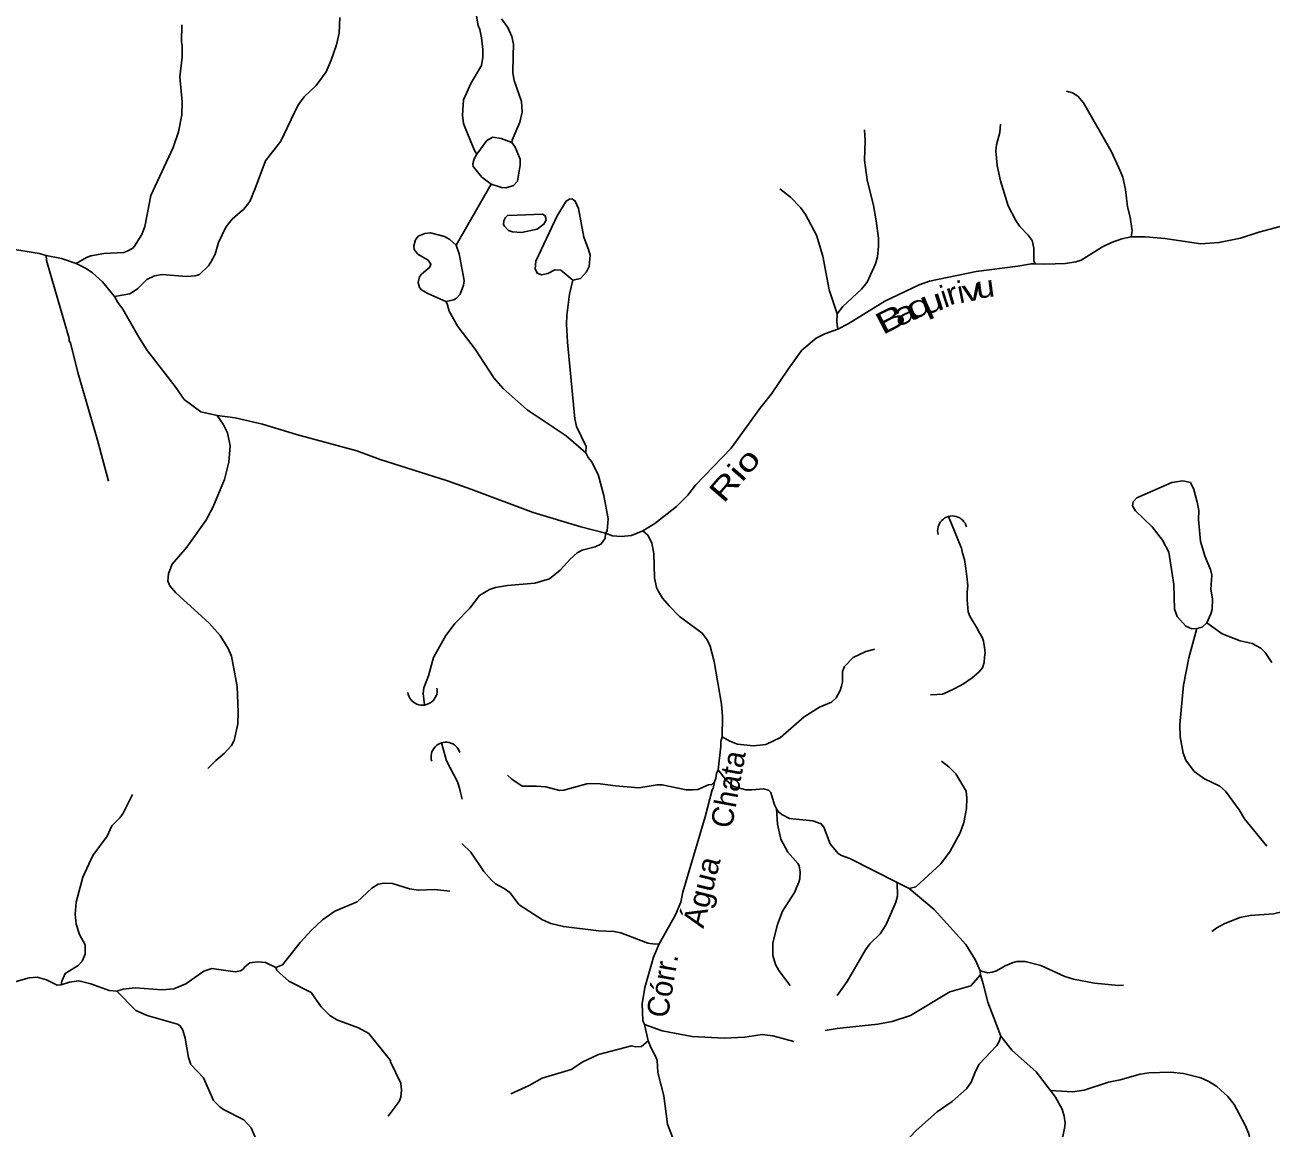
# Model space of a CAD drawing. Extents: x 346.5 to 372.4, y 7400.3 to 7428.2.
# Drawn here: x 354.02 to 358.605, y 7406.713 to 7410.774 of the extents above; entities that cross this region are included whole.
import ezdxf
from ezdxf.enums import TextEntityAlignment as Align

# ---------------------------------------------------------------- set-up
doc = ezdxf.new("R2010")
doc.units = 0
doc.header["$LTSCALE"] = 0.032
for name, color, linetype, lineweight in [('1', 7, 'Continuous', 25), ('11', 7, 'Continuous', 25), ('2', 7, 'Continuous', 25), ('7', 7, 'Continuous', 25)]:
    doc.layers.add(name, color=color, linetype=linetype, lineweight=lineweight)
doc.layers.add('61', color=7, linetype='Continuous')

msp = doc.modelspace()

# ---------------------------------------------------------------- linework, layer by layer
at = {"layer": '1'}
msp.add_lwpolyline([(354.098, 7409.9245), (354.0997, 7409.9069), (354.1829, 7409.6193), (354.1829, 7409.6105), (354.1877, 7409.6033), (354.2148, 7409.4942), (354.2873, 7409.2455), (354.3272, 7409.0949)], dxfattribs=at)
at = {"layer": '11'}
for centre, start, end in [((357.4324, 7408.9121), 14.923, 195.626), ((355.4826, 7408.3238), 188.0692, 8.7722), ((355.5686, 7408.0796), 16.6975, 197.4005)]:
    msp.add_arc(centre, 0.0541, start, end, dxfattribs=at)
at = {"layer": '2'}
for points in [[(355.6824, 7410.2983), (355.72, 7410.3486), (355.7413, 7410.3602), (355.7728, 7410.3554), (355.8114, 7410.3405), (355.8241, 7410.324), (355.8422, 7410.2791), (355.8417, 7410.2571), (355.8329, 7410.1986), (355.8173, 7410.1829), (355.7911, 7410.1738), (355.7732, 7410.1747), (355.7357, 7410.1873), (355.7013, 7410.2133), (355.6696, 7410.2527), (355.6686, 7410.2621), (355.673, 7410.2802)], [(355.9442, 7409.8591), (355.9202, 7409.8538), (355.9049, 7409.8594), (355.8977, 7409.8755), (355.8996, 7409.9039), (355.9788, 7410.0713), (356.012, 7410.1253), (356.0236, 7410.1327), (356.0334, 7410.133), (356.0447, 7410.1254), (356.0569, 7410.0983), (356.0767, 7409.9922), (356.0943, 7409.9475), (356.0996, 7409.9256), (356.0958, 7409.8847), (356.0863, 7409.8648), (356.0642, 7409.8398), (356.036, 7409.8343), (355.992, 7409.8711), (355.9697, 7409.8727)], [(355.8315, 7410.0737), (355.9249, 7410.0767), (355.9344, 7410.0707), (355.9377, 7410.057), (355.9308, 7410.0414), (355.9048, 7410.022), (355.8474, 7410.0095), (355.8136, 7410.0122), (355.799, 7410.0171), (355.7841, 7410.0324), (355.7812, 7410.0391), (355.7826, 7410.0524), (355.7879, 7410.0644), (355.796, 7410.0724)], [(355.5687, 7409.7553), (355.5025, 7409.7855), (355.4795, 7409.7985), (355.4715, 7409.8067), (355.4669, 7409.8261), (355.4721, 7409.8462), (355.4795, 7409.8566), (355.5098, 7409.8819), (355.5137, 7409.8929), (355.5036, 7409.9077), (355.466, 7409.9303), (355.4523, 7409.9469), (355.4511, 7409.9605), (355.4576, 7409.9827), (355.4675, 7409.9955), (355.492, 7410.0055), (355.5121, 7410.0083), (355.5636, 7409.9947), (355.5834, 7409.9838), (355.6064, 7409.9625), (355.6178, 7409.9315), (355.6357, 7409.8333), (355.634, 7409.8158), (355.6217, 7409.782), (355.6085, 7409.768), (355.5986, 7409.7623)], [(358.2394, 7409.0893), (358.2805, 7409.0955), (358.3083, 7409.089), (358.3204, 7409.0642), (358.3333, 7409.0172), (358.3391, 7408.9863), (358.3378, 7408.9531), (358.3449, 7408.8726), (358.3623, 7408.8156), (358.3825, 7408.7694), (358.3868, 7408.7487), (358.3833, 7408.697), (358.39, 7408.6613), (358.388, 7408.6224), (358.3839, 7408.606), (358.3688, 7408.5728), (358.351, 7408.5574), (358.3322, 7408.5523), (358.3131, 7408.5512), (358.2917, 7408.5612), (358.2597, 7408.5967), (358.2492, 7408.6229), (358.2476, 7408.7145), (358.2289, 7408.8335), (358.2061, 7408.8777), (358.1673, 7408.9262), (358.1064, 7408.9856), (358.0951, 7409.0038), (358.0978, 7409.0184), (358.1118, 7409.0333)]]:
    msp.add_lwpolyline(points, close=True, dxfattribs=at)
at = {"layer": '7'}
msp.add_line((355.7357, 7410.1873), (355.6064, 7409.9625), dxfattribs=at)
for points in [[(355.6796, 7410.8187), (355.6875, 7410.7709), (355.6939, 7410.7565), (355.7003, 7410.7262), (355.7051, 7410.6832), (355.7051, 7410.6545), (355.7003, 7410.6242), (355.662, 7410.5605), (355.6333, 7410.4975), (355.6301, 7410.4409), (355.6341, 7410.4107), (355.6397, 7410.3947), (355.6741, 7410.3111), (355.6824, 7410.2983)], [(354.5973, 7410.7733), (354.5957, 7410.7119), (354.5989, 7410.6976), (354.5989, 7410.6545), (354.5901, 7410.5828), (354.5989, 7410.4903), (354.5973, 7410.4425), (354.5846, 7410.3804), (354.5654, 7410.323), (354.4833, 7410.1461), (354.4618, 7410.0313), (354.4507, 7410.0026), (354.4236, 7409.9596), (354.4172, 7409.9524), (354.3965, 7409.9404), (354.3837, 7409.9365), (354.3104, 7409.9317), (354.2626, 7409.9237), (354.2467, 7409.9181), (354.209, 7409.895)], [(355.1791, 7410.8012), (355.1759, 7410.7438), (355.1663, 7410.7007), (355.1472, 7410.6434), (355.1281, 7410.6003), (355.0914, 7410.5509), (355.0476, 7410.5087), (355.0245, 7410.4776), (354.9623, 7410.3453), (354.9049, 7410.2736), (354.8667, 7410.1716), (354.8475, 7410.1238), (354.8252, 7410.0951), (354.8125, 7410.0847), (354.783, 7410.0592), (354.7599, 7410.0297), (354.7328, 7409.9723), (354.72, 7409.9293), (354.7041, 7409.9006), (354.6953, 7409.8863), (354.6627, 7409.8552), (354.6467, 7409.8504), (354.6149, 7409.848), (354.5256, 7409.8544), (354.4969, 7409.8504), (354.4682, 7409.8368), (354.4339, 7409.8026), (354.4061, 7409.7842), (354.3493, 7409.7734)], [(355.7736, 7410.7964), (355.7975, 7410.7637), (355.8119, 7410.731), (355.8182, 7410.7023), (355.8166, 7410.6593), (355.815, 7410.5971), (355.8206, 7410.5685), (355.8469, 7410.4919), (355.8501, 7410.4529), (355.8405, 7410.4154), (355.8124, 7410.3496), (355.8114, 7410.3405)], [(357.8528, 7410.5302), (357.8744, 7410.523), (357.8943, 7410.5111), (357.915, 7410.4872), (358.0162, 7410.3086), (358.0449, 7410.2481), (358.0592, 7410.2138), (358.0696, 7410.1684), (358.0768, 7410.1046), (358.0863, 7410.0664), (358.0935, 7410.0154), (358.0908, 7409.9932)], [(357.6098, 7410.4083), (357.6074, 7410.3772), (357.5946, 7410.3326), (357.5922, 7410.3102), (357.5978, 7410.256), (357.609, 7410.2003), (357.6377, 7410.1078), (357.6663, 7410.0536), (357.6807, 7410.0313), (357.7118, 7409.9994), (357.7261, 7409.9795), (357.7325, 7409.9516), (357.7321, 7409.9056), (357.7377, 7409.8945)], [(357.1093, 7410.3875), (357.1117, 7410.3469), (357.1093, 7410.2752), (357.1188, 7410.2034), (357.142, 7410.1094), (357.1523, 7410.052), (357.1603, 7409.9883), (357.1611, 7409.9596), (357.1571, 7409.9197), (357.1499, 7409.8942), (357.1188, 7409.8273), (357.0981, 7409.801), (357.0296, 7409.7372), (357.0087, 7409.7101)], [(356.7977, 7410.17), (356.8367, 7410.1397), (356.8742, 7410.1014), (356.8917, 7410.0759), (356.9324, 7409.9994), (356.9555, 7409.9229), (356.9786, 7409.7986), (357.0087, 7409.7101)], [(358.0908, 7409.9932), (358.1437, 7409.993), (358.2139, 7409.9875), (358.3462, 7409.9675), (358.4131, 7409.9723), (358.4928, 7409.989), (358.5597, 7410.0106), (358.7351, 7410.0568)], [(357.7377, 7409.8945), (357.7724, 7409.8934), (357.8489, 7409.8958), (357.8871, 7409.9014), (357.9062, 7409.9078), (357.9851, 7409.9564), (358.0186, 7409.9723), (358.0561, 7409.9859), (358.0908, 7409.9932)], [(353.9677, 7409.95), (354.0729, 7409.9317), (354.098, 7409.9245), (354.1542, 7409.9141), (354.209, 7409.895)], [(354.209, 7409.895), (354.2458, 7409.8775), (354.2682, 7409.8608), (354.3056, 7409.8281), (354.3431, 7409.781), (354.3493, 7409.7734)], [(357.0109, 7409.6543), (357.0487, 7409.6735), (357.1842, 7409.7571), (357.3109, 7409.8169), (357.3484, 7409.8305), (357.5205, 7409.8655), (357.6735, 7409.8854), (357.7232, 7409.8945), (357.7377, 7409.8945)], [(356.036, 7409.8343), (356.0238, 7409.7827), (356.0143, 7409.7046), (356.0127, 7409.6727), (356.0159, 7409.6057), (356.043, 7409.3236), (356.0501, 7409.2949), (356.0846, 7409.2216), (356.0839, 7409.1989)], [(354.3493, 7409.7734), (354.3614, 7409.7516), (354.3805, 7409.7269), (354.4387, 7409.6241), (354.4714, 7409.5739), (354.5734, 7409.4432), (354.6061, 7409.3945), (354.6674, 7409.3491), (354.728, 7409.3364)], [(355.5687, 7409.7553), (355.5741, 7409.7471), (355.5807, 7409.7205), (355.6126, 7409.6631), (355.6764, 7409.5802), (355.7449, 7409.475), (355.78, 7409.4352), (355.8676, 7409.3571), (356.0119, 7409.2614), (356.0839, 7409.1989)], [(357.0087, 7409.7101), (357.0068, 7409.679), (357.0109, 7409.6543)], [(356.2933, 7408.9116), (356.3379, 7408.9379), (356.4175, 7409.0016), (356.459, 7409.0431), (356.4877, 7409.0797), (356.6192, 7409.216), (356.7236, 7409.3619), (356.7666, 7409.4161), (356.8279, 7409.5069), (356.879, 7409.5762), (356.9308, 7409.6201), (356.9627, 7409.6368), (357.0109, 7409.6543)], [(354.728, 7409.3364), (354.7495, 7409.3045), (354.7655, 7409.2726), (354.7758, 7409.2248), (354.7702, 7409.1642), (354.7543, 7409.1005), (354.7121, 7408.9969), (354.6858, 7408.9491), (354.6156, 7408.8518), (354.5614, 7408.7889), (354.5487, 7408.7546), (354.5455, 7408.7259), (354.5535, 7408.7092), (354.575, 7408.6829), (354.6985, 7408.5721), (354.7384, 7408.5259), (354.7679, 7408.4789), (354.7798, 7408.4502), (354.8013, 7408.3386), (354.8053, 7408.2446), (354.8029, 7408.2015), (354.7894, 7408.1394), (354.7806, 7408.121), (354.7543, 7408.0931), (354.7224, 7408.066), (354.693, 7408.0366)], [(354.728, 7409.3364), (354.7934, 7409.3268), (354.8938, 7409.3037), (355.0197, 7409.2662), (355.2413, 7409.2064), (355.3273, 7409.1746), (355.5744, 7409.0957), (355.6604, 7409.0646), (355.89, 7408.9785), (356.0653, 7408.9259), (356.1567, 7408.9023)], [(356.0839, 7409.1989), (356.0928, 7409.1811), (356.1051, 7409.1666), (356.129, 7409.1188), (356.1505, 7409.0415), (356.1665, 7408.9554), (356.1623, 7408.9119), (356.1567, 7408.9023)], [(357.4182, 7408.9643), (357.4644, 7408.8503), (357.4656, 7408.848), (357.4702, 7408.8295), (357.4767, 7408.8055), (357.4825, 7408.7733), (357.4854, 7408.7429), (357.4889, 7408.709), (357.4872, 7408.6867), (357.4866, 7408.658), (357.4889, 7408.6276), (357.4907, 7408.6136), (357.4971, 7408.5972), (357.5088, 7408.5768), (357.5211, 7408.5575), (357.5339, 7408.5335), (357.5427, 7408.5207), (357.5468, 7408.5055), (357.5503, 7408.4821), (357.5526, 7408.4634), (357.5509, 7408.4464), (357.5497, 7408.4267), (357.5433, 7408.4074), (357.5298, 7408.3911), (357.5053, 7408.3706), (357.4732, 7408.3484), (357.441, 7408.3314), (357.413, 7408.3174), (357.3966, 7408.3098), (357.375, 7408.3092), (357.3522, 7408.3081)], [(355.49, 7408.2717), (355.4891, 7408.2812), (355.4859, 7408.3131), (355.4875, 7408.3338), (355.505, 7408.3784), (355.5234, 7408.4454), (355.5688, 7408.5267), (355.6031, 7408.5721), (355.6565, 7408.6263), (355.6931, 7408.6733), (355.729, 7408.6956), (355.7513, 7408.7028), (355.7959, 7408.7108), (355.8963, 7408.7187), (355.9497, 7408.7347), (355.9896, 7408.7673), (356.0262, 7408.8072), (356.0525, 7408.8303), (356.0701, 7408.8407), (356.1179, 7408.8526), (356.1394, 7408.8622), (356.1546, 7408.8831), (356.1567, 7408.9023)], [(356.1567, 7408.9023), (356.1826, 7408.8935), (356.2135, 7408.8901), (356.2518, 7408.894), (356.2933, 7408.9116)], [(356.2933, 7408.9116), (356.3131, 7408.8949), (356.3267, 7408.8662), (356.3339, 7408.8279), (356.337, 7408.7387), (356.3442, 7408.7028), (356.3514, 7408.6877), (356.3665, 7408.6637), (356.3904, 7408.635), (356.4287, 7408.596), (356.5116, 7408.5346), (356.5307, 7408.5107), (356.5419, 7408.4868), (356.5562, 7408.431), (356.5833, 7408.2732), (356.5865, 7408.2286), (356.5859, 7408.1533)], [(358.3688, 7408.5728), (358.4258, 7408.5322), (358.4912, 7408.5067), (358.5358, 7408.4964), (358.5669, 7408.4797), (358.5828, 7408.4637), (358.6083, 7408.4263)], [(358.3322, 7408.5523), (358.3023, 7408.4438), (358.2832, 7408.3434), (358.2696, 7408.1983), (358.2712, 7408.1537), (358.2816, 7408.0931), (358.2919, 7408.0676), (358.3222, 7408.0262), (358.3605, 7407.9991), (358.4163, 7407.9712), (358.4378, 7407.9529), (358.488, 7407.8843), (358.5079, 7407.8509), (358.5892, 7407.7512)], [(357.1467, 7408.4757), (357.1141, 7408.4669), (357.067, 7408.4454), (357.0352, 7408.4119), (357.028, 7408.3936), (357.028, 7408.3561), (357.0248, 7408.3402), (357.02, 7408.3243), (357.0049, 7408.2963), (356.9874, 7408.2812), (356.9435, 7408.2621), (356.8877, 7408.227), (356.8001, 7408.1513), (356.7459, 7408.125), (356.7013, 7408.1202), (356.6423, 7408.1258), (356.6136, 7408.137), (356.5859, 7408.1533)], [(355.5527, 7408.1314), (355.5712, 7408.0644), (355.6118, 7407.9879), (355.619, 7407.964), (355.6222, 7407.9489), (355.6286, 7407.9234)], [(356.5859, 7408.1533), (356.5804, 7408.1361), (356.5809, 7408.1186), (356.5711, 7408.0319)], [(357.3922, 7408.0636), (357.4201, 7408.0429), (357.4456, 7408.0166), (357.4838, 7407.9529), (357.4862, 7407.9274), (357.4846, 7407.8891), (357.4743, 7407.8381), (357.4607, 7407.7999), (357.4249, 7407.7321), (357.3898, 7407.6859), (357.2982, 7407.6014), (357.274, 7407.5952)], [(356.5711, 7408.0319), (356.5642, 7408.0181), (356.5626, 7408.0015), (356.5577, 7407.9878)], [(356.7856, 7407.8887), (356.7777, 7407.9035), (356.765, 7407.9489), (356.7562, 7407.9568), (356.7371, 7407.9624), (356.6949, 7407.9576), (356.6726, 7407.9584), (356.6269, 7407.9699), (356.6007, 7407.994), (356.5711, 7408.0319)], [(355.7959, 7408.0126), (355.8119, 7407.9975), (355.8501, 7407.9712), (355.9019, 7407.972), (355.9362, 7407.9688), (355.9872, 7407.956), (356.0031, 7407.9568), (356.0876, 7407.9808), (356.1036, 7407.9815), (356.137, 7407.9808), (356.1928, 7407.9728), (356.2789, 7407.9656), (356.3458, 7407.9768), (356.3649, 7407.976), (356.4526, 7407.9584), (356.4765, 7407.9576), (356.4956, 7407.9592), (356.5355, 7407.976), (356.5475, 7407.9779), (356.5577, 7407.9878)], [(356.5577, 7407.9878), (356.5529, 7407.963), (356.549, 7407.9584), (356.5227, 7407.8588), (356.4406, 7407.5815), (356.4339, 7407.5448), (356.4143, 7407.4978), (356.3535, 7407.3917)], [(354.4164, 7407.9409), (354.3805, 7407.87), (354.3694, 7407.8548), (354.3399, 7407.8254), (354.3232, 7407.7871), (354.2698, 7407.7162), (354.2331, 7407.6373), (354.2092, 7407.5448), (354.2044, 7407.5002), (354.2084, 7407.4635), (354.2211, 7407.4253), (354.2419, 7407.3878), (354.2419, 7407.3536), (354.2307, 7407.3281), (354.2164, 7407.3113), (354.1686, 7407.2826), (354.1562, 7407.2537), (354.1538, 7407.2408)], [(356.7856, 7407.8887), (356.7889, 7407.8317), (356.8017, 7407.776), (356.8272, 7407.7289), (356.8638, 7407.6875), (356.8686, 7407.6779), (356.8726, 7407.6564), (356.8718, 7407.6309), (356.8678, 7407.6182), (356.8511, 7407.5799), (356.808, 7407.5122), (356.7889, 7407.462), (356.7714, 7407.395), (356.7714, 7407.3488), (356.7817, 7407.3153), (356.7945, 7407.293), (356.8359, 7407.238)], [(357.2293, 7407.6166), (357.0551, 7407.705), (357.024, 7407.7162), (357.0129, 7407.7241), (356.9834, 7407.76), (356.9595, 7407.8206), (356.9499, 7407.8325), (356.9196, 7407.8445), (356.8336, 7407.8532), (356.8048, 7407.8674), (356.7918, 7407.8784), (356.7856, 7407.8887)], [(356.3535, 7407.3917), (356.3387, 7407.3902), (356.3124, 7407.3942), (356.2127, 7407.4316), (356.188, 7407.4364), (356.1306, 7407.4388), (356.0015, 7407.4548), (355.9553, 7407.4667), (355.925, 7407.4803), (355.839, 7407.5353), (355.8039, 7407.5799), (355.7832, 7407.595), (355.7521, 7407.6118), (355.7369, 7407.6261), (355.709, 7407.658), (355.6612, 7407.7289), (355.6278, 7407.7608)], [(355.5831, 7407.5855), (355.5266, 7407.591), (355.4676, 7407.5887), (355.4357, 7407.5942), (355.372, 7407.6134), (355.3417, 7407.615), (355.3194, 7407.611), (355.297, 7407.5966), (355.2428, 7407.5456), (355.16, 7407.5113), (355.1153, 7407.4795), (355.0747, 7407.442), (355.0324, 7407.3966), (354.9679, 7407.3137), (354.9434, 7407.3038)], [(357.2293, 7407.6166), (357.2304, 7407.5672), (357.2248, 7407.5448), (357.189, 7407.4627), (357.1667, 7407.4285), (357.1292, 7407.391), (357.1125, 7407.3695), (357.0455, 7407.2532), (357.0081, 7407.2014)], [(357.5352, 7407.2914), (357.5173, 7407.3313), (357.4822, 7407.3886), (357.3659, 7407.5177), (357.274, 7407.5952), (357.2293, 7407.6166)], [(358.7158, 7407.5211), (358.6857, 7407.5185), (358.6139, 7407.5018), (358.5279, 7407.4954), (358.4896, 7407.4882), (358.4322, 7407.4651), (358.4051, 7407.4508), (358.3868, 7407.4372)], [(356.3535, 7407.3917), (356.3323, 7407.3424), (356.3012, 7407.2308), (356.2916, 7407.1703), (356.294, 7407.1097), (356.2992, 7407.0949), (356.3134, 7407.0341)], [(354.3583, 7407.2173), (354.3821, 7407.2245), (354.4252, 7407.2292), (354.5256, 7407.2221), (354.5686, 7407.2252), (354.6117, 7407.2436), (354.6786, 7407.2906), (354.7073, 7407.3002), (354.7934, 7407.2882), (354.8133, 7407.2922), (354.8236, 7407.2986), (354.8292, 7407.3065), (354.8476, 7407.3209), (354.8763, 7407.3249), (354.9049, 7407.3225), (354.9434, 7407.3038)], [(354.9434, 7407.3038), (354.9474, 7407.2943), (354.9567, 7407.2842), (354.991, 7407.2539), (355.0739, 7407.2117), (355.1097, 7407.1599), (355.1424, 7407.1272), (355.1679, 7407.1121), (355.2476, 7407.0826), (355.2851, 7407.0611), (355.3656, 7406.9623), (355.3656, 7406.9567), (355.4038, 7406.8786), (355.4062, 7406.8531), (355.4038, 7406.8276), (355.3974, 7406.8108), (355.356, 7406.7567)], [(358.0616, 7407.2388), (358.0433, 7407.238), (357.9557, 7407.2468), (357.8776, 7407.2611), (357.8457, 7407.2715), (357.758, 7407.3113), (357.6998, 7407.3265), (357.6703, 7407.3265), (357.656, 7407.3225), (357.6273, 7407.3105), (357.5954, 7407.2914), (357.5795, 7407.2874), (357.5636, 7407.285), (357.5352, 7407.2914)], [(357.6107, 7407.0517), (357.5627, 7407.1766), (357.546, 7407.2436), (357.5366, 7407.2769), (357.5352, 7407.2914)], [(353.9789, 7407.2507), (354.0363, 7407.2667), (354.065, 7407.2683), (354.0992, 7407.2587), (354.1387, 7407.2394), (354.1538, 7407.2408)], [(354.1538, 7407.2408), (354.1845, 7407.2507), (354.218, 7407.2547), (354.2626, 7407.2444), (354.3303, 7407.2197), (354.3583, 7407.2173)], [(357.5366, 7407.2769), (357.5006, 7407.2364), (357.4233, 7407.2149), (357.2782, 7407.128), (357.2113, 7407.1057), (357.1587, 7407.0961), (357.0089, 7407.0802), (356.965, 7407.0722)], [(354.3583, 7407.2173), (354.4276, 7407.1456), (354.4698, 7407.128), (354.5814, 7407.0961), (354.5909, 7407.0898), (354.6005, 7407.073), (354.6101, 7407.0444), (354.622, 7406.9726), (354.6308, 7406.9471), (354.677, 7406.8977), (354.7145, 7406.8148), (354.7376, 7406.7909), (354.7503, 7406.7821), (354.8252, 7406.7439), (354.8531, 7406.7144), (354.8786, 7406.6539)], [(356.8487, 7407.0316), (356.7714, 7407.0523), (356.7331, 7407.0571), (356.6694, 7407.0483), (356.5929, 7407.0443), (356.4749, 7407.0499), (356.3649, 7407.0714), (356.2992, 7407.0949)], [(356.3134, 7407.0341), (356.2892, 7407.0133), (356.2661, 7407.0125), (356.2518, 7407.0156), (356.1306, 7406.9838), (356.0733, 7406.9567), (356.0302, 7406.9288), (355.9234, 7406.8969), (355.8756, 7406.8698), (355.8079, 7406.8387)], [(356.3134, 7407.0341), (356.324, 7407.0076), (356.3418, 7406.9758), (356.3458, 7406.9615), (356.3482, 7406.9184), (356.3713, 7406.8324), (356.3841, 7406.7272), (356.4024, 7406.6794), (356.4155, 7406.6286), (356.4203, 7406.6148)], [(357.6107, 7407.0517), (357.6049, 7407.0322), (357.5962, 7407.0172), (357.5317, 7406.9487), (357.5189, 7406.9256), (357.5014, 7406.8818), (357.4846, 7406.8571), (357.4321, 7406.8108), (357.3771, 7406.7726), (357.3006, 7406.7056), (357.2193, 7406.6212), (357.1563, 7406.5463)], [(357.7933, 7406.8513), (357.7405, 7406.92), (357.6512, 7406.9997), (357.6107, 7407.0517)], [(358.5765, 7406.5765), (358.5541, 7406.5973), (358.5294, 7406.6602), (358.5231, 7406.6921), (358.5103, 7406.724), (358.4697, 7406.8005), (358.4466, 7406.8292), (358.4051, 7406.8658), (358.3764, 7406.8849), (358.3462, 7406.8985), (358.2824, 7406.9136), (358.2346, 7406.9192), (358.1549, 7406.916), (358.123, 7406.912), (358.0497, 7406.8913), (358.0067, 7406.8826), (357.9174, 7406.8523), (357.8744, 7406.8467), (357.7933, 7406.8513)], [(357.8316, 7406.6697), (357.8391, 7406.6828), (357.8457, 7406.7192), (357.8473, 7406.732), (357.8441, 7406.7575), (357.8361, 7406.783), (357.8114, 7406.8268), (357.7933, 7406.8513)]]:
    msp.add_lwpolyline(points, dxfattribs=at)

# ---------------------------------------------------------------- texts
at = {"layer": '61'}
for s, rotation, p in [('i', 17.911, (357.4151, 7409.7357)), ('i', 11.31, (357.471, 7409.7509)), ('Chata', 79.459, (356.6468, 7407.9533)), ('Córr.', 80.233, (356.4049, 7407.2323))]:
    msp.add_text(s, height=0.08, rotation=rotation, dxfattribs=at).set_placement(p, align=Align.CENTER)
for s, rotation, width, p in [('r', 16.273, 1.15, (357.4416, 7409.7466)), ('v', 11.31, 1.3, (357.5113, 7409.7583)), ('u', 7.715, 1.15, (357.5582, 7409.7703)), ('q', 23.858, 1.55, (357.3233, 7409.7027)), ('u', 17.911, 1.4, (357.3689, 7409.7172)), ('B', 27.474, 1.5, (357.2229, 7409.6554)), ('a', 23.858, 1.4, (357.2714, 7409.6781)), ('Rio', 48.966, 1.35, (356.6615, 7409.0912)), ('Água', 75.964, 1.05, (356.5483, 7407.5729))]:
    msp.add_text(s, height=0.08, rotation=rotation, dxfattribs=dict(at, width=width)).set_placement(p, align=Align.CENTER)

doc.saveas('drawing.dxf')
